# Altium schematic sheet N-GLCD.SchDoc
size A4
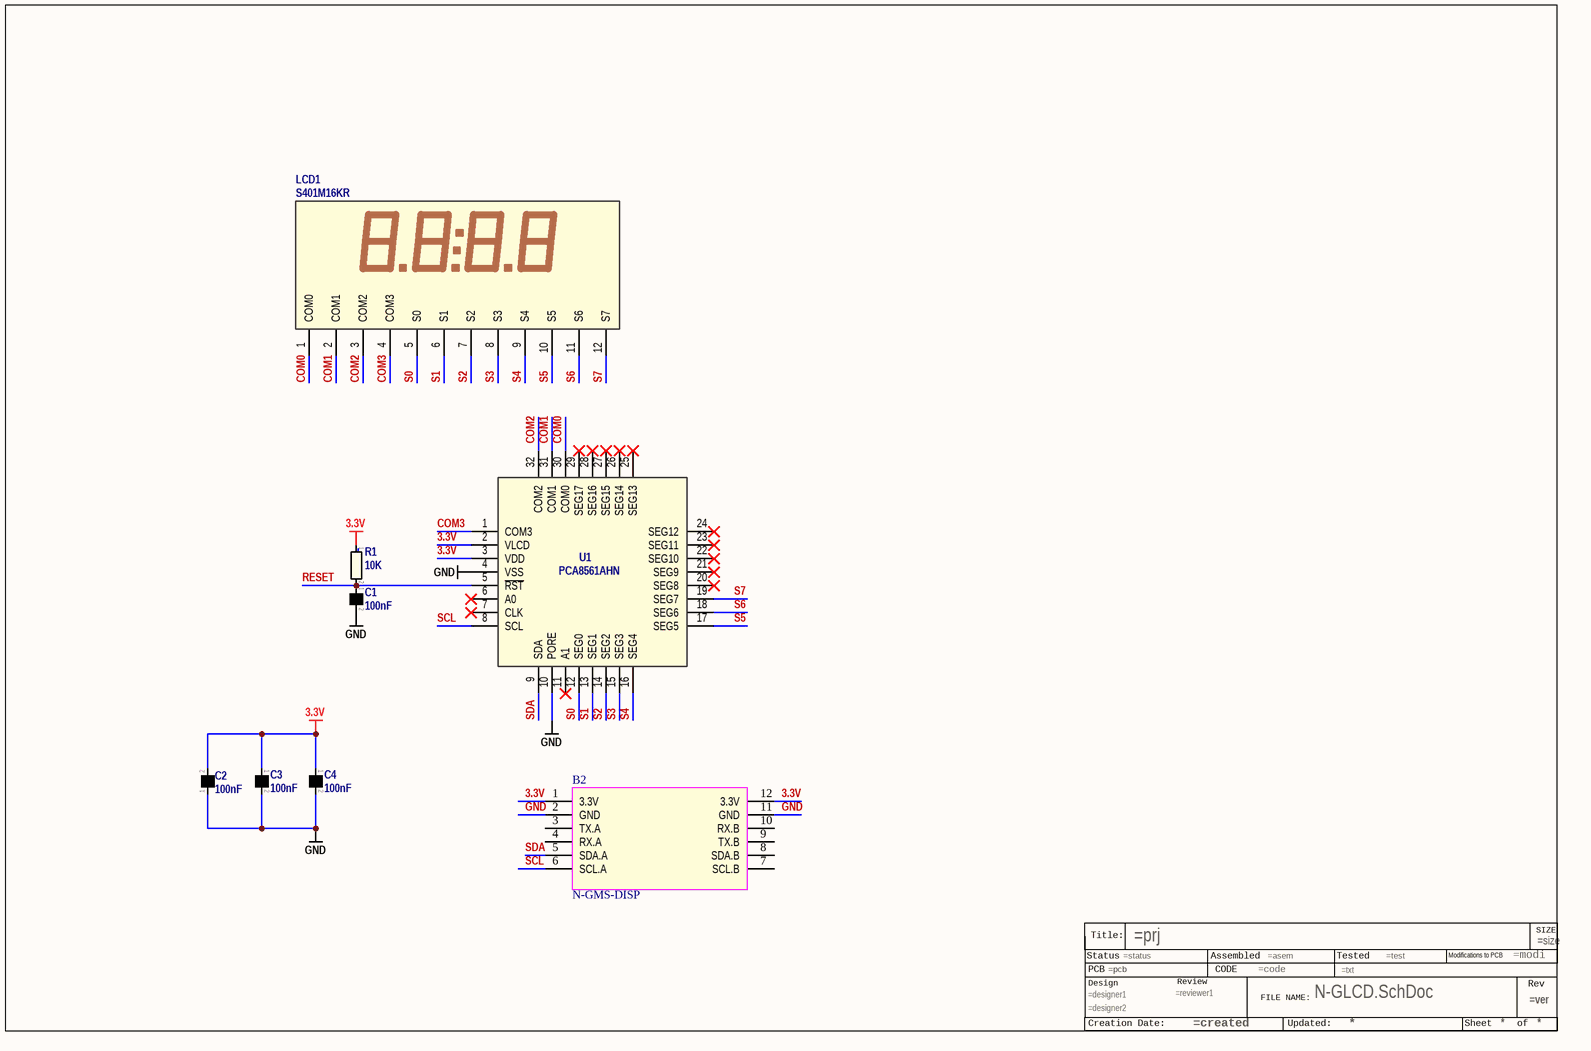
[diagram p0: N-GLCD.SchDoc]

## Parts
?*??  FILE_NAME: N-GLCD.SchDoc  (hidden comment: TITLEBLOCK3)  (graphical)
B2  N-GMS-DISP  [N-GMS-DISP]
C1  100nF  [0603_cap]
C2  100nF  [0603_cap]
C3  100nF  [0603_cap]
C4  100nF  [0603_cap]
LCD1  S401M16KR  [LCD-S401M16KR]
R1  10K  [0603_res]
U1  PCA8561AHN  [QFN32-HVQFN32_0.5mm_LONG]

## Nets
3.3V: B2.1(3.3V) B2.12(3.3V) C2.2 C3.1 C4.1 R1.1 U1.2(VLCD) U1.3(VDD)
GND: B2.2(GND) B2.11(GND) C1.2 C2.1 C3.2 C4.2 U1.4(VSS) U1.10(PORE)
COM0: LCD1.1(COM0) U1.30(COM0)
COM1: LCD1.2(COM1) U1.31(COM1)
COM2: LCD1.3(COM2) U1.32(COM2)
COM3: LCD1.4(COM3) U1.1(COM3)
RESET: C1.1 R1.2 U1.5(~{RST})
S0: LCD1.5(S0) U1.12(SEG0)
S1: LCD1.6(S1) U1.13(SEG1)
S2: LCD1.7(S2) U1.14(SEG2)
S3: LCD1.8(S3) U1.15(SEG3)
S4: LCD1.9(S4) U1.16(SEG4)
S5: LCD1.10(S5) U1.17(SEG5)
S6: LCD1.11(S6) U1.18(SEG6)
S7: LCD1.12(S7) U1.19(SEG7)
SCL: B2.6(SCL.A) U1.8(SCL)
SDA: B2.5(SDA.A) U1.9(SDA)

Not connected (* = marked no-connect by the designer): ?*?? ?1; B2 3(TX.A) 4(RX.A) 7(SCL.B) 8(SDA.B) 9(TX.B) 10(RX.B); U1 6(A0)* 7(CLK)* 11(A1)* 20(SEG8)* 21(SEG9)* 22(SEG10)* 23(SEG11)* 24(SEG12)* 25(SEG13)* 26(SEG14)* 27(SEG15)* 28(SEG16)* 29(SEG17)*

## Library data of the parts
C1-C4 = C: CAPACITOR
LCD1 = LCD-S401M16KR
R1 = R: RESISTOR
